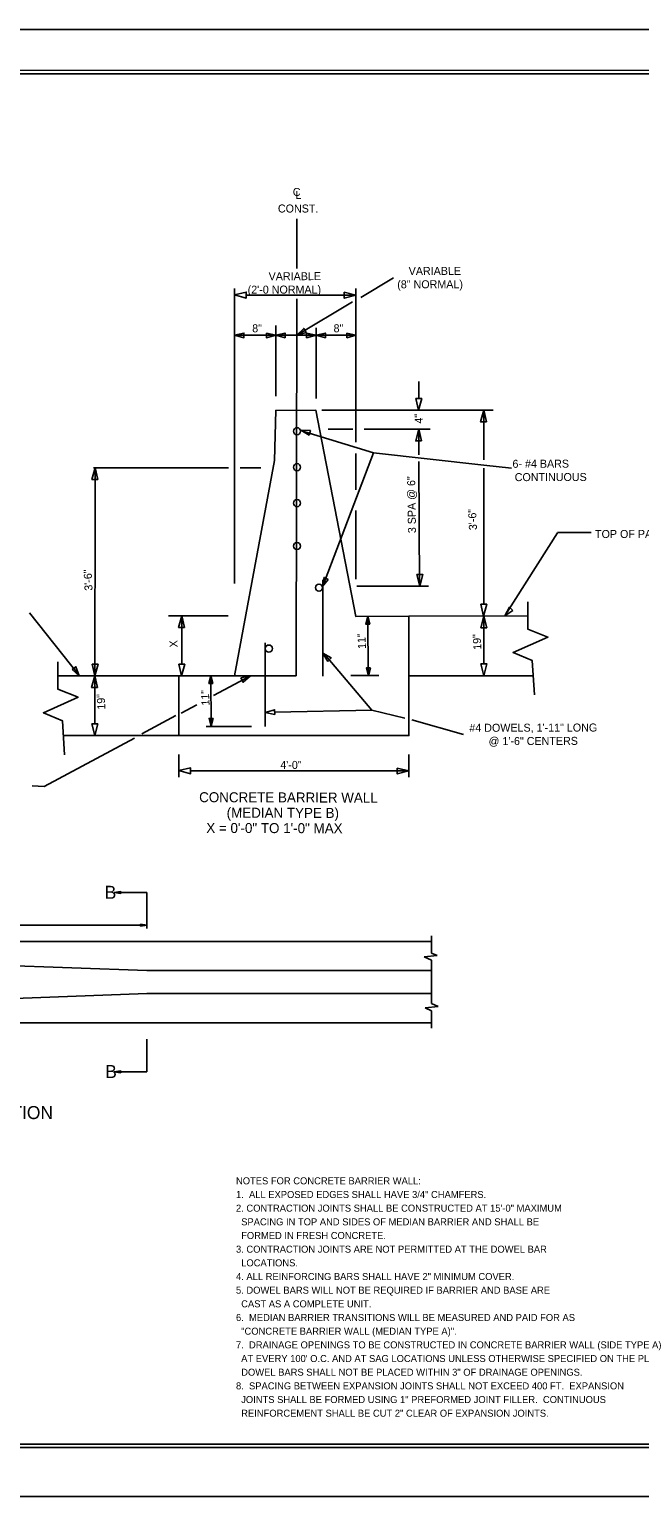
# Model space of a CAD drawing. Extents: x 714919 to 718439, y 1619644 to 1621844.
# Drawn here: x 716327 to 717241, y 1619644 to 1621844 of the extents above; entities that cross this region are included whole.
import ezdxf

# ---------------------------------------------------------------- set-up
doc = ezdxf.new("R2010")
doc.units = 0
for name, color, linetype in [('Level 1', 7, 'Continuous'), ('R_Annotation', 7, 'Continuous'), ('R_Border', 7, 'Continuous'), ('R_Border Notes', 7, 'Continuous'), ('R_Centerline', 7, 'Continuous'), ('R_Dimension', 7, 'Continuous'), ('R_No Plot', 7, 'Continuous'), ('T_Drafting', 7, 'Continuous'), ('T_Notes', 7, 'Continuous')]:
    doc.layers.add(name, color=color, linetype=linetype)

msp = doc.modelspace()

# ---------------------------------------------------------------- linework, layer by layer
at = {"layer": 'Level 1'}
for p, q in [((716727.4, 1621485.4), (716727.4, 1621559.6)), ((716823.3, 1621442), (716872.4, 1621471.4)), ((716634.3, 1621047.6), (716634.3, 1621455.2)), ((716816, 1621224.8), (716816, 1621455.2)), ((716651.9, 1621445.5), (716816, 1621445.5)), ((716726.8, 1620874.7), (716727.4, 1621439.9)), ((716727.4, 1621385.1), (716810.7, 1621435.1)), ((716634.3, 1621385.1), (716695.9, 1621385.1)), ((716695.9, 1621385.1), (716756.3, 1621385.1)), ((716696, 1621293.7), (716696, 1621399.7)), ((716756.3, 1621290.4), (716756.3, 1621396.2)), ((716756.3, 1621385.2), (716816, 1621385.2)), ((716910.3, 1621290.2), (716910.3, 1621315.9)), ((716765.2, 1621272.6), (717021.7, 1621272.6)), ((717007.5, 1621198.5), (717007.5, 1621272.6)), ((716733, 1621242.5), (716842.6, 1621208.9)), ((716774.7, 1621244.2), (716811.2, 1621244.2)), ((716828.6, 1621244.2), (716927.1, 1621244.2)), ((716910.4, 1621206), (716910.3, 1621244.2)), ((716765.8, 1621008.1), (716842.6, 1621208.9)), ((716816, 1621153.5), (716816, 1621207.9)), ((716842.6, 1621208.9), (717007.5, 1621190.5)), ((716625, 1621186.6), (716423, 1621186.6)), ((716425.3, 1621136.4), (716425.3, 1621186.6)), ((716673.7, 1621186.6), (716642.7, 1621186.6)), ((716911.2, 1621008.9), (716910.5, 1621195.9)), ((717007.5, 1621190.5), (717049, 1621185.9)), ((717007.5, 1620981.7), (717007.5, 1621186)), ((716425.1, 1620874.3), (716425.3, 1621136.4)), ((716816, 1621019.4), (716816, 1621122.3)), ((717039, 1620964.2), (717118.3, 1621089.1)), ((717118.1, 1621089.2), (717168.6, 1621089.5)), ((716634.3, 1621013), (716634.3, 1621047.6)), ((716766.4, 1621018.5), (716766.4, 1620873.8)), ((716817.6, 1621008.9), (716924.7, 1621008.9)), ((716401.9, 1620874.3), (716326.9, 1620969)), ((716624.5, 1620964.4), (716535.2, 1620964.4)), ((716555.2, 1620891.9), (716555.2, 1620964.4)), ((716834.2, 1620875), (716834, 1620963.4)), ((717073.5, 1620964.3), (716895.4, 1620963.8)), ((717007.9, 1620892.3), (717007.9, 1620964.1)), ((716680.2, 1620924.1), (716680.2, 1620798.4)), ((716839.9, 1620823.1), (716768.3, 1620907.3)), ((716550.8, 1620874.3), (716369.6, 1620874.3)), ((716425, 1620802.4), (716425, 1620874.3)), ((716550.8, 1620874.3), (716634.3, 1620874.7)), ((716599.2, 1620798.7), (716598.9, 1620874.6)), ((716657.9, 1620874.7), (716602.7, 1620845.2)), ((716634.3, 1620874.7), (716726.8, 1620874.7)), ((716850.6, 1620875), (716808.4, 1620875)), ((717081.6, 1620874.7), (716895.4, 1620874.7)), ((716577.9, 1620831.2), (716554.3, 1620818.6)), ((716546.2, 1620814.9), (716495.2, 1620787.6)), ((716840.3, 1620823), (716694.3, 1620820)), ((716889.3, 1620811.2), (716839.9, 1620823.1)), ((716977.4, 1620786.3), (716899.8, 1620808.5)), ((716659.4, 1620798.7), (716591.8, 1620798.7)), ((716484.3, 1620781.1), (716348.8, 1620708.7)), ((716550.8, 1620784.8), (716377.7, 1620784.8)), ((716550.8, 1620756.7), (716550.8, 1620722.5)), ((716895.4, 1620756.7), (716895.4, 1620722.5)), ((716568.4, 1620732), (716895.4, 1620732)), ((716348.8, 1620708.7), (716331.1, 1620709.4))]:
    msp.add_line(p, q, dxfattribs=at)
for points in [[(716634.3, 1621445.7), (716651.9, 1621449.9), (716651.9, 1621441)], [(716798.5, 1621449.6), (716798.5, 1621440.7), (716816, 1621445.5)], [(716634.3, 1621385.1), (716648.4, 1621388.5), (716648.4, 1621381.4)], [(716681.9, 1621388.5), (716681.9, 1621381.4), (716696, 1621385.1)], [(716695.9, 1621385.1), (716710, 1621388.5), (716710, 1621381.4)], [(716741.3, 1621389.2), (716737.8, 1621395.4), (716727.4, 1621385.1)], [(716742.2, 1621388.5), (716742.2, 1621381.4), (716756.3, 1621385.1)], [(716756.3, 1621385.2), (716770.3, 1621388.5), (716770.3, 1621381.4)], [(716802.5, 1621388.5), (716802.5, 1621381.4), (716816, 1621385.2)], [(716905.8, 1621290.2), (716914.7, 1621290.2), (716910, 1621272.6)], [(717011.7, 1621255.1), (717002.8, 1621255.1), (717007.5, 1621272.6)], [(716745.9, 1621235.5), (716748, 1621242.3), (716733.5, 1621243)], [(716914.4, 1621226.6), (716905.6, 1621226.7), (716910.3, 1621244.2)], [(716429.5, 1621169), (716420.6, 1621169), (716425.3, 1621186.6)], [(716774.7, 1621019.1), (716768.3, 1621022.1), (716765.7, 1621007.7)], [(716907.4, 1621026.5), (716916.3, 1621026.5), (716911.6, 1621008.9)], [(716559.3, 1620946.8), (716550.4, 1620946.8), (716555.2, 1620964.4)], [(716834, 1620963.4), (716836.8, 1620951.7), (716830.8, 1620951.7)], [(717003.1, 1620981.7), (717012, 1620981.7), (717007.3, 1620964.1)], [(717012, 1620946.5), (717003.2, 1620946.5), (717007.9, 1620964.1)], [(717051.2, 1620972.5), (717045.9, 1620977.2), (717039.3, 1620964.2)], [(716774, 1620896.2), (716779, 1620901.3), (716766.3, 1620908.5)], [(716390.8, 1620884), (716396.6, 1620888), (716401.6, 1620874.3)], [(716429.1, 1620856.8), (716420.2, 1620856.8), (716425, 1620874.3)], [(716420.9, 1620891.9), (716429.8, 1620891.9), (716425.1, 1620874.3)], [(716550.7, 1620891.9), (716559.6, 1620891.9), (716554.9, 1620874.4)], [(716598.9, 1620874.6), (716601.7, 1620862.8), (716595.8, 1620862.8)], [(716643.9, 1620871.3), (716647.1, 1620864.9), (716657.9, 1620874.7)], [(716837.8, 1620886.7), (716831.8, 1620886.7), (716835, 1620875)], [(717003.4, 1620892.3), (717012.3, 1620892.3), (717007.6, 1620874.7)], [(716602, 1620810.5), (716596, 1620810.5), (716599.2, 1620798.7)], [(716694.4, 1620816.5), (716694.2, 1620823.6), (716680.2, 1620819.6)], [(716420.5, 1620802.4), (716429.4, 1620802.3), (716424.7, 1620784.8)], [(716550.8, 1620732.3), (716568.4, 1620736.5), (716568.4, 1620727.6)], [(716877.9, 1620736.2), (716877.9, 1620727.3), (716895.4, 1620732)]]:
    msp.add_lwpolyline(points, close=True, dxfattribs=at)
for points in [[(716651.9, 1621441), (716651.9, 1621449.9), (716634.3, 1621445.7), (716651.9, 1621441)], [(716651.9, 1621441), (716651.9, 1621449.9), (716634.3, 1621445.7), (716651.9, 1621441)], [(716648.4, 1621381.4), (716648.4, 1621388.5), (716634.3, 1621385.1), (716648.4, 1621381.4)], [(716648.4, 1621381.4), (716648.4, 1621388.5), (716634.3, 1621385.1), (716648.4, 1621381.4)], [(716710, 1621381.4), (716710, 1621388.5), (716695.9, 1621385.1), (716710, 1621381.4)], [(716710, 1621381.4), (716710, 1621388.5), (716695.9, 1621385.1), (716710, 1621381.4)], [(716770.3, 1621381.4), (716770.3, 1621388.5), (716756.3, 1621385.2), (716770.3, 1621381.4)], [(716770.3, 1621381.4), (716770.3, 1621388.5), (716756.3, 1621385.2), (716770.3, 1621381.4)], [(716550.8, 1620874.3), (716550.8, 1620784.8), (716895.4, 1620784.8), (716895.4, 1620963.8), (716816, 1620963.3), (716756.2, 1621272.6), (716695.9, 1621272.5), (716694.3, 1621197.2), (716634.3, 1620874.7)], [(717073.5, 1620985.5), (717073.5, 1620944.5), (717103.6, 1620932.5), (717051.6, 1620909.3), (717080.1, 1620897.3), (717083.4, 1620846)], [(716830.8, 1620951.7), (716836.8, 1620951.7), (716834, 1620963.4), (716830.8, 1620951.7)], [(716830.8, 1620951.7), (716836.8, 1620951.7), (716834, 1620963.4), (716830.8, 1620951.7)], [(716369.6, 1620895.4), (716369.6, 1620854.4), (716399.8, 1620842.4), (716347.8, 1620819.1), (716376.3, 1620807.2), (716379.5, 1620755.8)], [(716595.8, 1620862.8), (716601.7, 1620862.8), (716598.9, 1620874.6), (716595.8, 1620862.8)], [(716595.8, 1620862.8), (716601.7, 1620862.8), (716598.9, 1620874.6), (716595.8, 1620862.8)], [(716568.4, 1620727.6), (716568.4, 1620736.5), (716550.8, 1620732.3), (716568.4, 1620727.6)], [(716568.4, 1620727.6), (716568.4, 1620736.5), (716550.8, 1620732.3), (716568.4, 1620727.6)]]:
    msp.add_lwpolyline(points, dxfattribs=at)
for centre in [(716727.8, 1621241.2), (716727.8, 1621187.3), (716727.8, 1621133.4), (716727.8, 1621069.1), (716760.7, 1621006.7), (716685.6, 1620915.3)]:
    msp.add_circle(centre, 5.33, dxfattribs=at)
at = {"layer": 'R_Border'}
for p, q in [((718438.8, 1621843.9), (714918.8, 1621843.6)), ((715231.1, 1621777.2), (718392.9, 1621777.2)), ((718393, 1619722.6), (715231, 1619722.6)), ((714918.9, 1619643.7), (718439.1, 1619643.9))]:
    msp.add_line(p, q, dxfattribs=at)
at = {"layer": 'R_Dimension'}
for p, q in [((716463.9, 1620551), (716454.1, 1620549.5)), ((716454.1, 1620549.5), (716503, 1620549.5)), ((716463.9, 1620548), (716454.1, 1620549.5)), ((716463.9, 1620550.7), (716455.7, 1620549.5)), ((716463.9, 1620548.3), (716455.7, 1620549.5)), ((716463.9, 1620550.5), (716457.4, 1620549.5)), ((716463.9, 1620548.5), (716457.4, 1620549.5)), ((716463.9, 1620550.2), (716459, 1620549.5)), ((716463.9, 1620548.8), (716459, 1620549.5)), ((716463.9, 1620550), (716460.7, 1620549.5)), ((716463.9, 1620549), (716460.7, 1620549.5)), ((716463.9, 1620549.7), (716462.3, 1620549.5)), ((716463.9, 1620549.3), (716462.3, 1620549.5)), ((716463.9, 1620548), (716463.9, 1620551)), ((716503, 1620495.8), (716503, 1620549.5)), ((715281.9, 1620500.7), (716503, 1620500.7)), ((716493.2, 1620502.1), (716503, 1620500.7)), ((716493.2, 1620502.1), (716493.2, 1620499.2)), ((716493.2, 1620501.9), (716501.3, 1620500.7)), ((716493.2, 1620501.7), (716499.7, 1620500.7)), ((716493.2, 1620501.4), (716498, 1620500.7)), ((716493.2, 1620501.1), (716496.4, 1620500.7)), ((716493.2, 1620500.9), (716494.7, 1620500.7)), ((716493.2, 1620499.2), (716503, 1620500.7)), ((716493.2, 1620500.2), (716496.4, 1620500.7)), ((716493.2, 1620499.7), (716499.7, 1620500.7)), ((716493.2, 1620499.4), (716501.3, 1620500.7)), ((716493.2, 1620499.9), (716498, 1620500.7)), ((716493.2, 1620500.4), (716494.7, 1620500.7)), ((716929.3, 1620484.4), (716929.3, 1620458.8)), ((716929.3, 1620458.8), (716937.6, 1620454.9)), ((716918.1, 1620453.3), (716937.6, 1620454.9)), ((716918.1, 1620453.3), (716929.3, 1620448)), ((716929.3, 1620448), (716929.3, 1620383)), ((716919.7, 1620376.8), (716939.2, 1620378.4)), ((716919.7, 1620376.8), (716929.3, 1620372.3)), ((716929.3, 1620383), (716939.2, 1620378.4)), ((716929.3, 1620372.3), (716929.3, 1620346)), ((716503, 1620329.7), (716503, 1620280.9)), ((716463.9, 1620282.3), (716454.1, 1620280.9)), ((716454.1, 1620280.9), (716503, 1620280.9)), ((716463.9, 1620279.4), (716454.1, 1620280.9)), ((716463.9, 1620282.1), (716455.7, 1620280.9)), ((716463.9, 1620279.7), (716455.7, 1620280.9)), ((716463.9, 1620281.9), (716457.4, 1620280.9)), ((716463.9, 1620279.9), (716457.4, 1620280.9)), ((716463.9, 1620281.6), (716459, 1620280.9)), ((716463.9, 1620280.1), (716459, 1620280.9)), ((716463.9, 1620281.4), (716460.7, 1620280.9)), ((716463.9, 1620280.4), (716460.7, 1620280.9)), ((716463.9, 1620281.1), (716462.3, 1620280.9)), ((716463.9, 1620280.6), (716462.3, 1620280.9)), ((716463.9, 1620279.4), (716463.9, 1620282.3))]:
    msp.add_line(p, q, dxfattribs=at)
at = {"layer": 'R_No Plot'}
msp.add_lwpolyline([(715227, 1619717.4), (718396.9, 1619717.5), (718397, 1621782.6), (715226.9, 1621782.4)], close=True, dxfattribs=at)
at = {"layer": 'T_Drafting'}
for p, q in [((715281.9, 1620476.2), (716929.3, 1620476.2)), ((715281.9, 1620476.2), (716503, 1620432.5)), ((716503, 1620432.5), (716929.3, 1620432.5)), ((715281.9, 1620354.1), (716503, 1620397.9)), ((716503, 1620397.9), (716929.3, 1620397.9)), ((715281.9, 1620354.1), (716929.3, 1620354.1))]:
    msp.add_line(p, q, dxfattribs=at)

# ---------------------------------------------------------------- texts
at = {"layer": 'R_Annotation'}
msp.add_text('CONCRETE BARRIER WALL (MEDIAN TYPE A) TRANSITION', height=19.537, dxfattribs=at).set_placement((715622, 1620209.8))
at = {"layer": 'R_Border Notes'}
for s, height, rotation, p in [('VARIABLE', 12, 0.1435, (716685.3, 1621467.6)), ('(8" NORMAL)', 12, 0.1435, (716878, 1621455.5)), ('VARIABLE', 12, 0.1435, (716895.1, 1621475.5)), ("(2'-0 NORMAL)", 12, 0.1435, (716653.9, 1621447.5)), ('8"', 12, 0.1435, (716660.7, 1621389.6)), ('8"', 12, 0.1435, (716782.6, 1621389.6)), ('4"', 12, 92.796, (716916.4, 1621253)), ('6- #4 BARS ', 12, 0.1435, (717050.6, 1621186.4)), ('3 SPA @ 6"', 12, 90.9227, (716906.1, 1621088.5)), ('CONTINUOUS', 12, 0.1435, (717054, 1621166.4)), ('3\'-6"', 12, 92.796, (716997.5, 1621093.2)), ('TOP OF PAVEMENT', 12, 0.1435, (717174.3, 1621081.1)), ('3\'-6"', 12, 92.796, (716421.6, 1621002.4)), ('X', 12, 92.796, (716549, 1620917.3)), ('11"', 12, 92.796, (716831.2, 1620915.1)), ('19"', 12, 92.796, (717004.1, 1620913.8)), ('11"', 12, 92.796, (716596.9, 1620830.2)), ('19"', 12, 92.796, (716440.8, 1620824.1)), ('#4 DOWELS, 1\'-11" LONG', 12, 0.1435, (716986, 1620790.5)), ('@ 1\'-6" CENTERS', 12, 0.1435, (717014.8, 1620770.6)), ('4\'-0"', 12, 0.1435, (716702.8, 1620734.8)), ('CONCRETE BARRIER WALL ', 15, 359.8477, (716581.2, 1620685)), ('(MEDIAN TYPE B) ', 15, 359.8477, (716622.4, 1620661.8)), ('X = 0\'-0" TO 1\'-0" MAX', 15, 359.8477, (716591.9, 1620638.9))]:
    msp.add_text(s, height=height, rotation=rotation, dxfattribs=at).set_placement(p)
at = {"layer": 'R_Centerline'}
for s, p in [('C', (716721.5, 1621594)), ('L', (716725.4, 1621589.5)), ('CONST.', (716699.2, 1621569.2))]:
    msp.add_text(s, height=12, dxfattribs=at).set_placement(p)
at = {"layer": 'R_Dimension'}
for p in [(716439.7, 1620540.1), (716440.5, 1620271.4)]:
    msp.add_text('B', height=19.5, dxfattribs=at).set_placement(p)
at = {"layer": 'T_Notes'}
for s, p in [('NOTES FOR CONCRETE BARRIER WALL:', (716636.4, 1620112)), ('2. CONTRACTION JOINTS SHALL BE CONSTRUCTED AT 15\'-0" MAXIMUM', (716636.4, 1620071)), ('1.  ALL EXPOSED EDGES SHALL HAVE 3/4" CHAMFERS.', (716636.4, 1620091.5)), ('  SPACING IN TOP AND SIDES OF MEDIAN BARRIER AND SHALL BE', (716636.4, 1620050.5)), ('  FORMED IN FRESH CONCRETE.', (716636.4, 1620030)), ('3. CONTRACTION JOINTS ARE NOT PERMITTED AT THE DOWEL BAR', (716636.4, 1620009.5)), ('  LOCATIONS.', (716636.4, 1619989)), ('4. ALL REINFORCING BARS SHALL HAVE 2" MINIMUM COVER.', (716636.4, 1619968.5)), ('5. DOWEL BARS WILL NOT BE REQUIRED IF BARRIER AND BASE ARE', (716636.4, 1619948)), ('  CAST AS A COMPLETE UNIT.', (716636.4, 1619927.5)), ('6.  MEDIAN BARRIER TRANSITIONS WILL BE MEASURED AND PAID FOR AS', (716636.4, 1619907)), ('  "CONCRETE BARRIER WALL (MEDIAN TYPE A)".', (716636.4, 1619886.5)), ('7.  DRAINAGE OPENINGS TO BE CONSTRUCTED IN CONCRETE BARRIER WALL (SIDE TYPE A)', (716636.4, 1619866)), ("  AT EVERY 100' O.C. AND AT SAG LOCATIONS UNLESS OTHERWISE SPECIFIED ON THE PLANS.", (716636.4, 1619845.5)), ('  DOWEL BARS SHALL NOT BE PLACED WITHIN 3" OF DRAINAGE OPENINGS.', (716636.4, 1619825)), ('8.  SPACING BETWEEN EXPANSION JOINTS SHALL NOT EXCEED 400 FT.  EXPANSION', (716636.4, 1619804.5)), ('  JOINTS SHALL BE FORMED USING 1" PREFORMED JOINT FILLER.  CONTINUOUS', (716636.4, 1619784)), ('  REINFORCEMENT SHALL BE CUT 2" CLEAR OF EXPANSION JOINTS.', (716636.4, 1619763.5))]:
    msp.add_text(s, height=10.5, dxfattribs=at).set_placement(p)

doc.saveas('drawing.dxf')
